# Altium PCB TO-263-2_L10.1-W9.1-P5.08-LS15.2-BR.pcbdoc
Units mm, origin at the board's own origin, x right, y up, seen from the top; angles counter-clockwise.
Board outline 29.64 x 23.31 mm, 2 copper layers (Top Layer, Bottom Layer), stack 0 mm thick; 1 components, 0 nets, 3 pads, 0 vias.
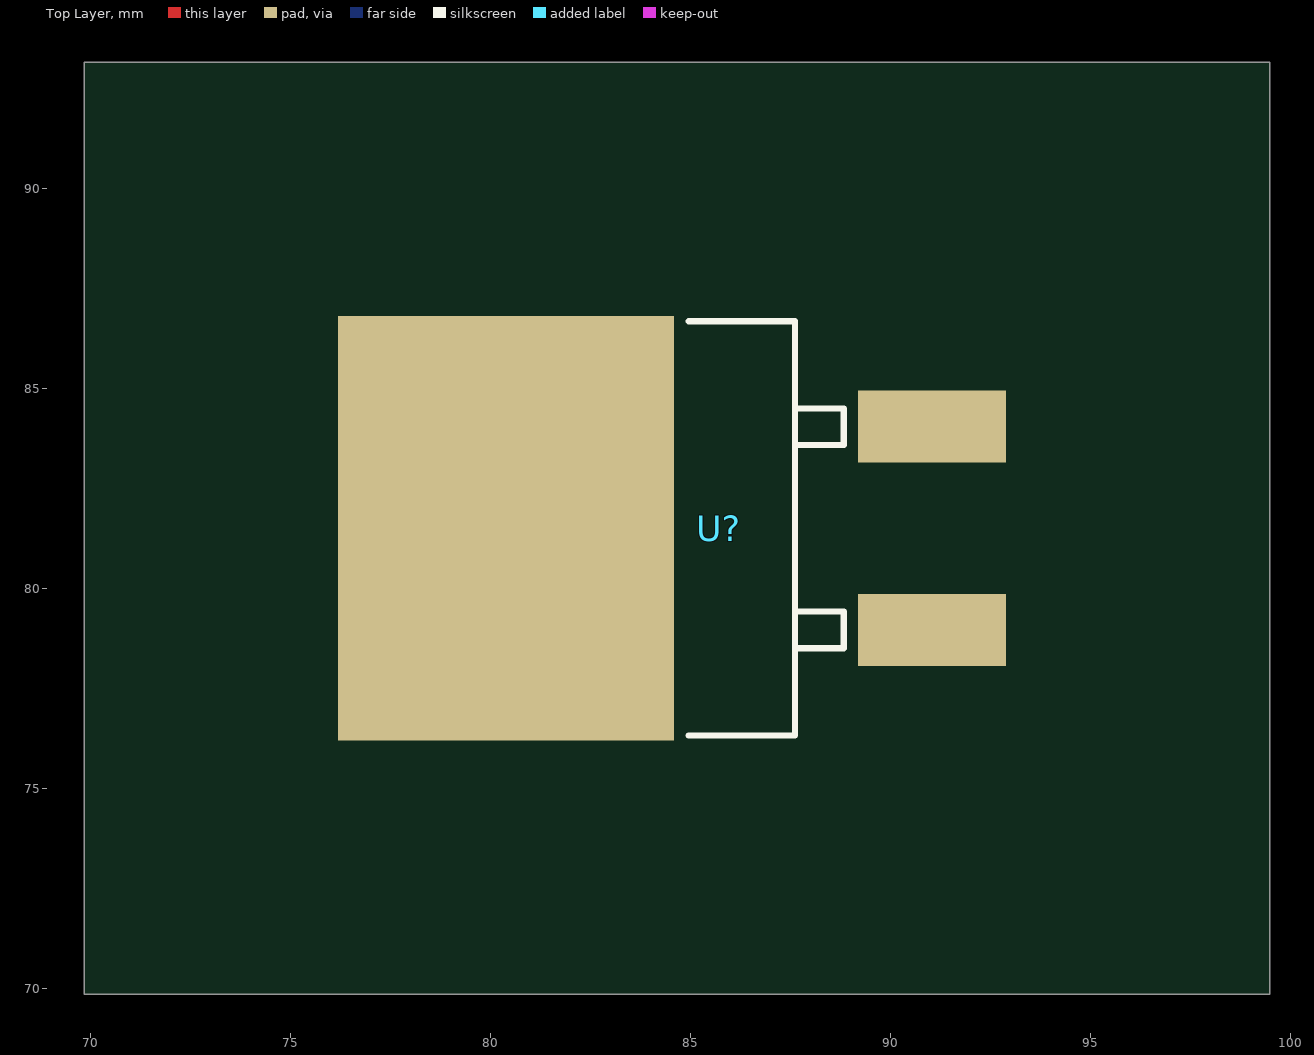
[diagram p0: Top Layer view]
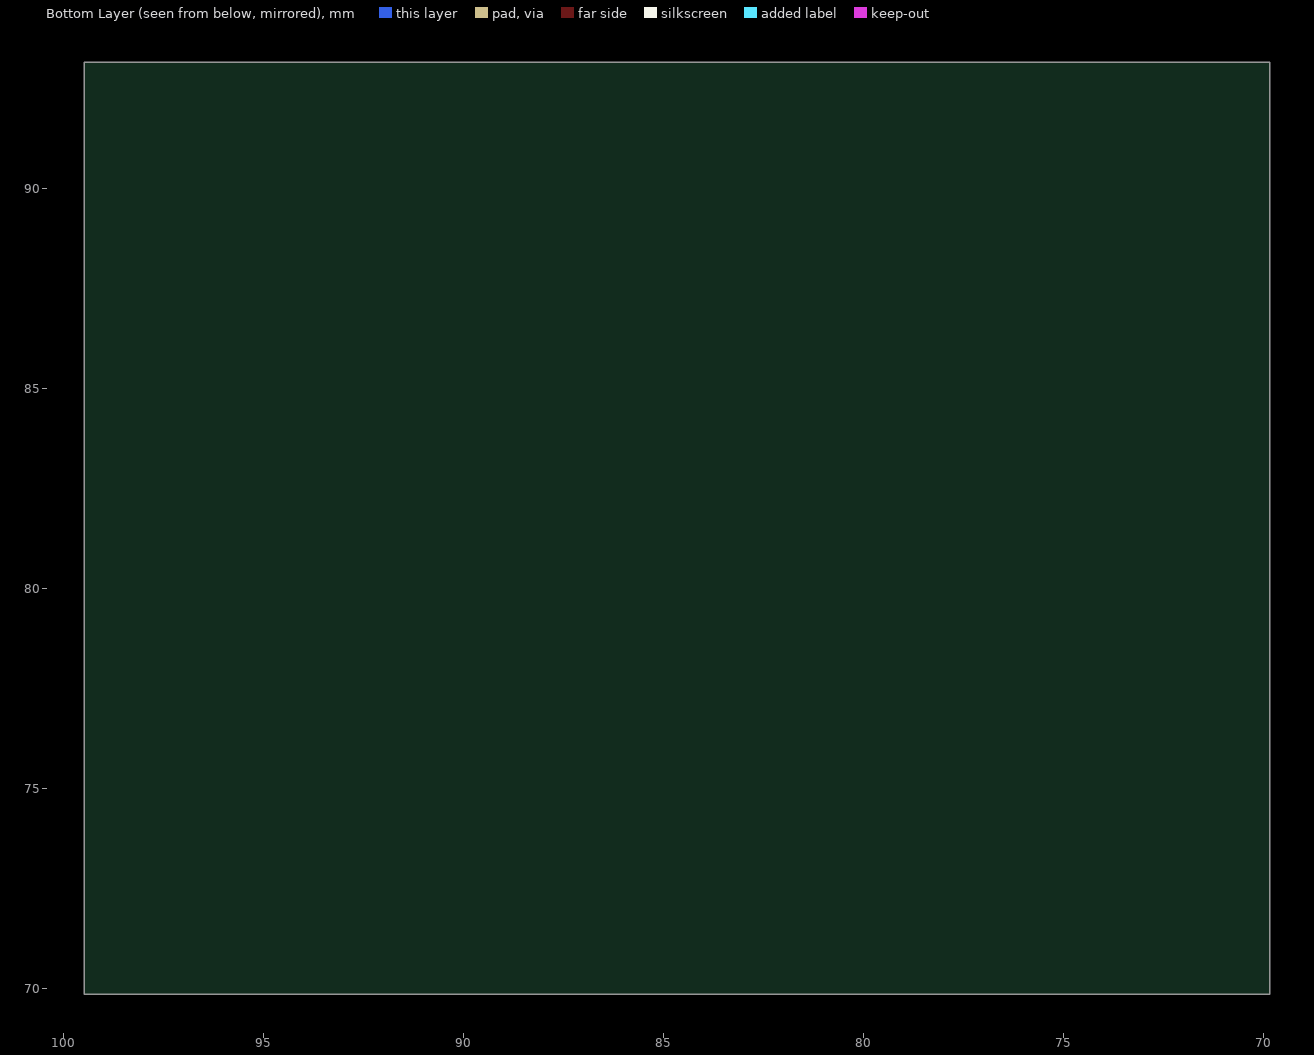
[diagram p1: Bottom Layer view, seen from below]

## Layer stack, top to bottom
Top Layer: signal copper (thickness not stored)
Bottom Layer: signal copper (thickness not stored)

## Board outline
99.494,69.85 69.85,69.85 69.85,93.158 99.494,93.158

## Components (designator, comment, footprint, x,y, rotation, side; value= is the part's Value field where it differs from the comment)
U? "" TO-263-2_L10.1-W9.1-P5.08-LS15.2-BR 85.721,81.504 r0 top

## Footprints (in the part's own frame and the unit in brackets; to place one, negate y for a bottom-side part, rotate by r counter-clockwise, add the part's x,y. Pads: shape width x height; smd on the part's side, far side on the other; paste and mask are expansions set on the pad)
TO-263-2_L10.1-W9.1-P5.08-LS15.2-BR [mm]
  rect 3.7x1.8 smd: 1(5.321,-2.54) 3(5.321,2.54)
  rect 8.4x10.608 smd: 2(-5.321,0)
  silkscreen extent -0.75,-5.18 3.12,5.18

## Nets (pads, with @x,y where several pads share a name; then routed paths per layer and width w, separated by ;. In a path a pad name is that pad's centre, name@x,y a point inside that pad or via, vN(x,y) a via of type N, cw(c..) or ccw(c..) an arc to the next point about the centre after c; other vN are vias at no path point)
pads on no net: U?.1 U?.2 U?.3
